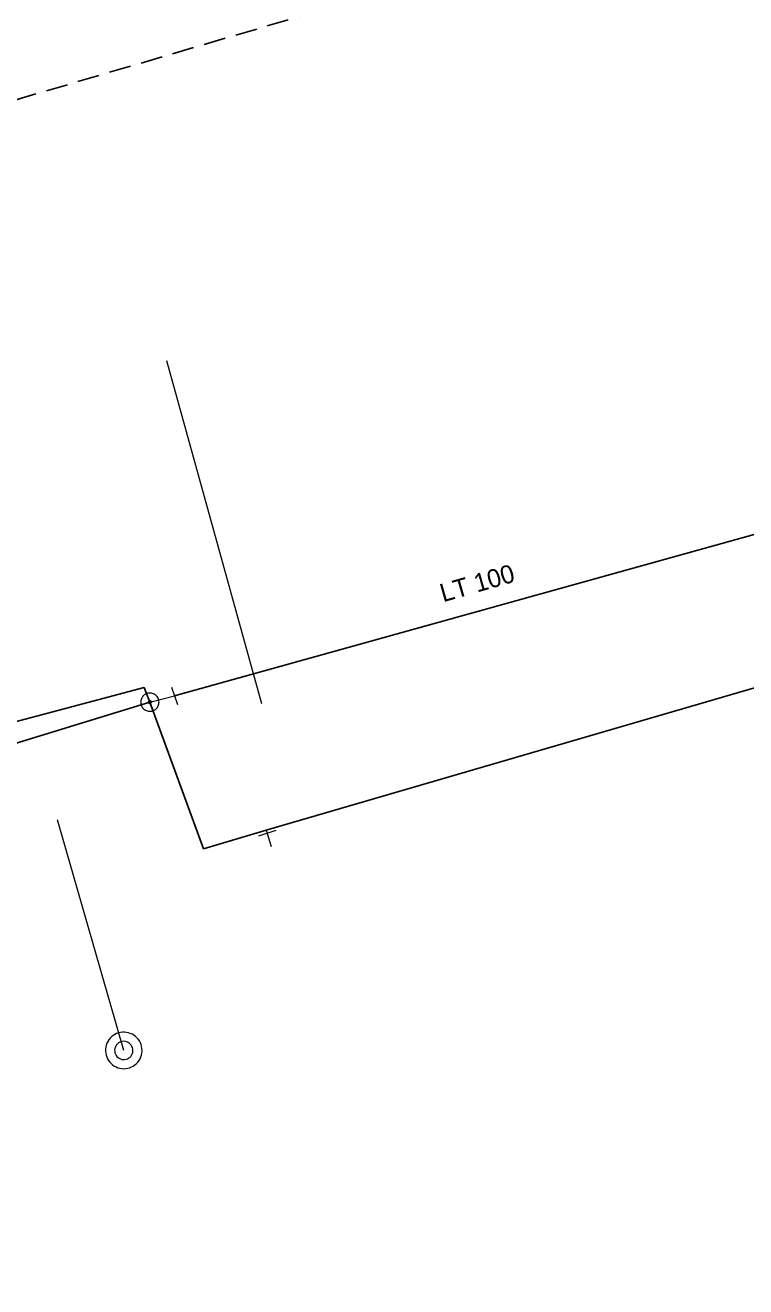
# Model space of a CAD drawing. Extents: x -690254 to -689100, y -975264 to -974703.
# Drawn here: x -690125 to -690085.5, y -975199.3 to -975130.2 of the extents above; entities that cross this region are included whole.
import ezdxf

# ---------------------------------------------------------------- set-up
doc = ezdxf.new("R2010")
doc.units = 0
doc.header["$LTSCALE"] = 0.4
doc.linetypes.add('MEDIUM_DASHED', pattern=[4.5, 3, -1.5])
for name, color, linetype, lineweight in [('1', 7, 'Continuous', 13), ('11', 7, 'Continuous', 13), ('13', 7, 'Continuous', 13), ('14', 7, 'Continuous', 13), ('17', 7, 'Continuous', 25), ('22', 7, 'Continuous', 13), ('34', 7, 'Continuous', 13), ('47', 7, 'Continuous', 13), ('63', 7, 'MEDIUM_DASHED', 25)]:
    doc.layers.add(name, color=color, linetype=linetype, lineweight=lineweight)

msp = doc.modelspace()

# ---------------------------------------------------------------- linework, layer by layer
at = {"layer": '11'}
for p, q in [((-690117.223, -975148.565), (-690112.027, -975167.335)), ((-690119.569, -975186.33), (-690123.2, -975173.704))]:
    msp.add_line(p, q, dxfattribs=at)
at = {"layer": '13'}
msp.add_line((-690111.726, -975174.447), (-690111.502, -975175.162), dxfattribs=at)
at = {"layer": '14'}
for p, q in [((-690118.142, -975167.265), (-690116.8, -975166.92)), ((-690111.773, -975174.27), (-690111.726, -975174.447))]:
    msp.add_line(p, q, dxfattribs=at)
at = {"layer": '17'}
msp.add_line((-690081.085, -975156.962), (-690116.8, -975166.92), dxfattribs=at)
for points in [[(-689651.896, -975035.605), (-689702.719, -975051.484), (-689800.052, -975078.399), (-689860.597, -975095.177), (-689913.514, -975110.178), (-689937.55, -975117.079), (-689948.793, -975119.833), (-689957.109, -975122.39), (-689986.109, -975129.956), (-690002.122, -975134.99), (-690005.949, -975136.193), (-690003.879, -975142.529), (-690036.781, -975151.448), (-690069.227, -975161.229), (-690080.424, -975165.129), (-690111.773, -975174.27), (-690115.204, -975175.288), (-690118.142, -975167.265)], [(-690118.142, -975167.265), (-690118.454, -975166.466), (-690151.024, -975175.128)], [(-690118.142, -975167.265), (-690135.219, -975172.5), (-690150.759, -975176.356)]]:
    msp.add_lwpolyline(points, dxfattribs=at)
at = {"layer": '22'}
for points in [[(-690118.569, -975186.33), (-690118.575, -975186.221), (-690118.593, -975186.113), (-690118.623, -975186.007), (-690118.663, -975185.906), (-690118.715, -975185.809), (-690118.777, -975185.719), (-690118.849, -975185.636), (-690118.929, -975185.562), (-690119.017, -975185.496), (-690119.111, -975185.441), (-690119.211, -975185.396), (-690119.316, -975185.363), (-690119.423, -975185.341), (-690119.532, -975185.331), (-690119.642, -975185.333), (-690119.75, -975185.347), (-690119.857, -975185.372), (-690119.96, -975185.409), (-690120.058, -975185.458), (-690120.15, -975185.516), (-690120.236, -975185.585), (-690120.313, -975185.662), (-690120.382, -975185.748), (-690120.441, -975185.84), (-690120.489, -975185.938), (-690120.526, -975186.041), (-690120.552, -975186.148), (-690120.566, -975186.256), (-690120.568, -975186.366), (-690120.558, -975186.475), (-690120.537, -975186.582), (-690120.503, -975186.686), (-690120.459, -975186.786), (-690120.404, -975186.881), (-690120.338, -975186.969), (-690120.264, -975187.049), (-690120.181, -975187.121), (-690120.091, -975187.183), (-690119.995, -975187.235), (-690119.893, -975187.276), (-690119.788, -975187.306), (-690119.68, -975187.324), (-690119.57, -975187.33), (-690119.461, -975187.324), (-690119.353, -975187.306), (-690119.248, -975187.277), (-690119.146, -975187.236), (-690119.049, -975187.184), (-690118.959, -975187.122), (-690118.876, -975187.051), (-690118.801, -975186.971), (-690118.736, -975186.883), (-690118.68, -975186.789), (-690118.636, -975186.689), (-690118.602, -975186.585), (-690118.58, -975186.477), (-690118.57, -975186.368)], [(-690119.069, -975186.33), (-690119.075, -975186.253), (-690119.093, -975186.178), (-690119.122, -975186.106), (-690119.162, -975186.04), (-690119.212, -975185.98), (-690119.27, -975185.929), (-690119.335, -975185.888), (-690119.406, -975185.857), (-690119.481, -975185.838), (-690119.558, -975185.83), (-690119.636, -975185.834), (-690119.711, -975185.851), (-690119.784, -975185.878), (-690119.851, -975185.917), (-690119.911, -975185.965), (-690119.963, -975186.023), (-690120.006, -975186.087), (-690120.038, -975186.157), (-690120.059, -975186.232), (-690120.069, -975186.309), (-690120.066, -975186.386), (-690120.051, -975186.462), (-690120.025, -975186.535), (-690119.988, -975186.603), (-690119.941, -975186.664), (-690119.885, -975186.718), (-690119.821, -975186.762), (-690119.751, -975186.796), (-690119.677, -975186.818), (-690119.601, -975186.829), (-690119.523, -975186.828), (-690119.447, -975186.815), (-690119.374, -975186.79), (-690119.305, -975186.755), (-690119.243, -975186.709), (-690119.188, -975186.654), (-690119.143, -975186.591), (-690119.107, -975186.522), (-690119.083, -975186.449), (-690119.071, -975186.372)]]:
    msp.add_lwpolyline(points, close=True, dxfattribs=at)
at = {"layer": '34'}
for p, q in [((-690116.967, -975166.448), (-690116.633, -975167.391)), ((-690111.248, -975174.297), (-690112.203, -975174.595))]:
    msp.add_line(p, q, dxfattribs=at)
at = {"layer": '47'}
for points in [[(-690117.655, -975167.149), (-690117.67, -975167.099), (-690117.69, -975167.05), (-690117.715, -975167.005), (-690117.744, -975166.961), (-690117.778, -975166.921), (-690117.816, -975166.885), (-690117.858, -975166.854), (-690117.902, -975166.826), (-690117.949, -975166.803), (-690117.998, -975166.785), (-690118.05, -975166.773), (-690118.102, -975166.767), (-690118.153, -975166.765), (-690118.206, -975166.769), (-690118.257, -975166.778), (-690118.307, -975166.793), (-690118.356, -975166.813), (-690118.402, -975166.838), (-690118.445, -975166.867), (-690118.485, -975166.901), (-690118.521, -975166.939), (-690118.553, -975166.981), (-690118.581, -975167.026), (-690118.604, -975167.072), (-690118.621, -975167.121), (-690118.633, -975167.173), (-690118.64, -975167.225), (-690118.641, -975167.276), (-690118.637, -975167.329), (-690118.628, -975167.38), (-690118.613, -975167.43), (-690118.593, -975167.479), (-690118.569, -975167.525), (-690118.539, -975167.568), (-690118.505, -975167.608), (-690118.468, -975167.644), (-690118.426, -975167.676), (-690118.381, -975167.704), (-690118.334, -975167.727), (-690118.285, -975167.744), (-690118.233, -975167.756), (-690118.182, -975167.763), (-690118.13, -975167.764), (-690118.077, -975167.76), (-690118.026, -975167.751), (-690117.976, -975167.736), (-690117.927, -975167.716), (-690117.882, -975167.692), (-690117.838, -975167.662), (-690117.798, -975167.628), (-690117.762, -975167.591), (-690117.731, -975167.549), (-690117.703, -975167.505), (-690117.68, -975167.457), (-690117.662, -975167.408), (-690117.65, -975167.356), (-690117.644, -975167.305), (-690117.642, -975167.253), (-690117.646, -975167.2)], [(-690118.062, -975167.246), (-690118.064, -975167.237), (-690118.068, -975167.229), (-690118.071, -975167.222), (-690118.076, -975167.215), (-690118.082, -975167.208), (-690118.088, -975167.203), (-690118.095, -975167.197), (-690118.102, -975167.192), (-690118.11, -975167.189), (-690118.118, -975167.186), (-690118.127, -975167.184), (-690118.135, -975167.183), (-690118.143, -975167.183), (-690118.152, -975167.183), (-690118.16, -975167.185), (-690118.169, -975167.187), (-690118.177, -975167.191), (-690118.184, -975167.194), (-690118.191, -975167.199), (-690118.198, -975167.205), (-690118.203, -975167.211), (-690118.209, -975167.218), (-690118.214, -975167.225), (-690118.218, -975167.233), (-690118.22, -975167.241), (-690118.222, -975167.25), (-690118.223, -975167.258), (-690118.223, -975167.266), (-690118.223, -975167.275), (-690118.221, -975167.283), (-690118.219, -975167.292), (-690118.215, -975167.3), (-690118.212, -975167.307), (-690118.207, -975167.314), (-690118.201, -975167.321), (-690118.196, -975167.327), (-690118.188, -975167.332), (-690118.181, -975167.337), (-690118.173, -975167.341), (-690118.165, -975167.343), (-690118.156, -975167.345), (-690118.148, -975167.346), (-690118.14, -975167.346), (-690118.131, -975167.346), (-690118.123, -975167.344), (-690118.114, -975167.342), (-690118.106, -975167.338), (-690118.099, -975167.335), (-690118.092, -975167.33), (-690118.085, -975167.324), (-690118.079, -975167.319), (-690118.074, -975167.311), (-690118.069, -975167.304), (-690118.066, -975167.296), (-690118.063, -975167.288), (-690118.061, -975167.279), (-690118.06, -975167.271), (-690118.06, -975167.263), (-690118.06, -975167.254)]]:
    msp.add_lwpolyline(points, close=True, dxfattribs=at)
at = {"layer": '63'}
msp.add_lwpolyline([(-690175.832, -975238.167), (-690201.511, -975156.663), (-690201.511, -975156.663), (-689696.859, -975008.171), (-689696.859, -975008.171), (-689730.354, -974917.735), (-689730.354, -974917.735), (-689127.452, -974763.66), (-689127.452, -974763.66), (-689118.52, -974838.465), (-689118.52, -974838.465), (-689624.288, -974970.21), (-689624.288, -974970.21), (-689593.026, -975070.694), (-689593.026, -975070.694)], close=True, dxfattribs=at)

# ---------------------------------------------------------------- texts
at = {"layer": '1'}
msp.add_text('LT 100', height=1, rotation=16, dxfattribs=at).set_placement((-690102.096, -975161.797))

doc.saveas('drawing.dxf')
